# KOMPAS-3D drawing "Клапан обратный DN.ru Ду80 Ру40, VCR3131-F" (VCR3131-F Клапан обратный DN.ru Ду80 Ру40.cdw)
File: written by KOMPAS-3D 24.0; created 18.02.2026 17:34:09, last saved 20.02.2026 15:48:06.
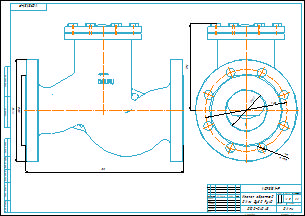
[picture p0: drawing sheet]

Document properties: art: D100-04043; Автор: R2D2; Форматы листов документа: A2; Полное имя файла: VCR3131-F Клапан обратный DN.ru Ду80 Ру40.m3d; Масса: 20.5; Наименование: Клапан обратный DN.ru Ду80 Ру40; Количество листов документа: 1; Примечание: D100-04043

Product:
- Part/product: Клапан обратный DN.ru Ду80 Ру40  | designation VCR3131-F
    Масса: 20.5
    Примечание: D100-04043
    additional columns: D100-04043

Views: Вид 1, Спереди, Проекционный вид 2
Referenced files in E:\Работа\Зайцев\VCR3131-F Клапан обратный DN.ru Ду15-300\DN80\: VCR3131-F Клапан обратный DN.ru Ду80 Ру40.m3d
Referenced files in E:\Работа\Зайцев\Для компаса\: чертеж DN.ru А3.cdt
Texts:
  VCR3131-F
  чертеж DN.ru А3.cdt
  Клапан обратный
  DN.ru Ду80 Ру40
  prop
  Клапан обратный DN.ru Ду80 Ру40
  VCR3131-F Клапан обратный DN.ru Ду80 Ру40
Dimensions and other numbers on the sheet: 0; 3; 2; 4; 170; 18; 8 отв.; 160; 80; 200; 138; 310; 1:1; 1; 20,5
